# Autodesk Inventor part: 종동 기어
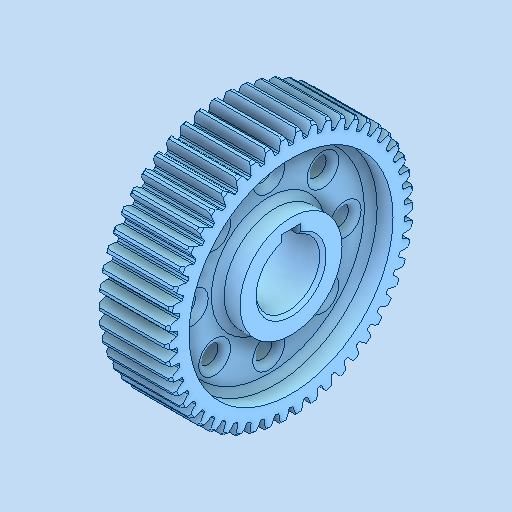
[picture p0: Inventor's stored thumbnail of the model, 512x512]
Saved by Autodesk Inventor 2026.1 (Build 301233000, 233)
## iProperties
Created: 2025-11
Part Number: 종동 기어
Material: 강철, 탄소
Document SubType Name: Modeling
Designer: PC-30
Density: 7.85 g/cm^3
Appearance: 기본값
Author: jhkim
Sending System: Autodesk Inventor 2026
Preprocessor: ST-DEVELOPER v20.1
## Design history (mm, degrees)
feature "솔리드1"
node "솔리드2"
